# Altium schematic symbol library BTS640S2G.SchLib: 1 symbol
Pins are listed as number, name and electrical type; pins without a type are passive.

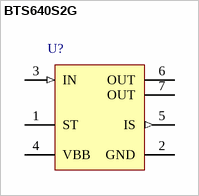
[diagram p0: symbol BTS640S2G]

## BTS640S2G
designator U?
Smart High-Side Power Switch, 1 Channel, 4.5 A Load Current, -40 to 150 degC, PG-TO-263-7-6, Reel, Green; Manufacturer: Infineon; PartNumber: BTS640S2G; Channels: 1; Green: TRUE; Group: Automotive Qualified; Load Current (typ): 4.5 A; Ptot (max): 85 W; Recommended Operating Voltage Max.: 34 V; Recommended Operating Voltage Min.: 5 V; RON @ 25degreesC: 30 mOhm; RON(max) @ 150degreesC: 60 mOhm; toff (max): 150 us; ton (max): 200 us
footprint INF-PG-TO-263-7-6_N (DPAK, 7-Leads, Body 9.9x9.2mm, Pitch 1.27mm, IPC Medium Density)
footprint INF-PG-TO-263-7-6_L (DPAK, 7-Leads, Body 9.9x9.2mm, Pitch 1.27mm, IPC High Density)
footprint INF-PG-TO-263-7-6_M (DPAK, 7-Leads, Body 9.9x9.2mm, Pitch 1.27mm, IPC Low Density)
pins: 1 ST (oc) "Diagnostic feedback: open drain, invers to input level", 2 GND (power) "Logic ground", 3 IN (in) "Input, activates the power switch in case of logical high signal", 4 VBB (power) "Positive power supply voltage, the tab is shorted to this pin", 5 IS (out) "Sense current output, proportional to the load current, zero in  the case of current limitation of load current", 6 OUT (power) "Output, protected high-side power output to the load.  Both output pins have to be connected in parallel for operation  according this spec (e.g. kILIS). Design the wiring for the max. short circuit current", 7 OUT (power) "Output, protected high-side power output to the load.  Both output pins have to be connected in parallel for operation  according this spec (e.g. kILIS). Design the wiring for the max. short circuit current"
